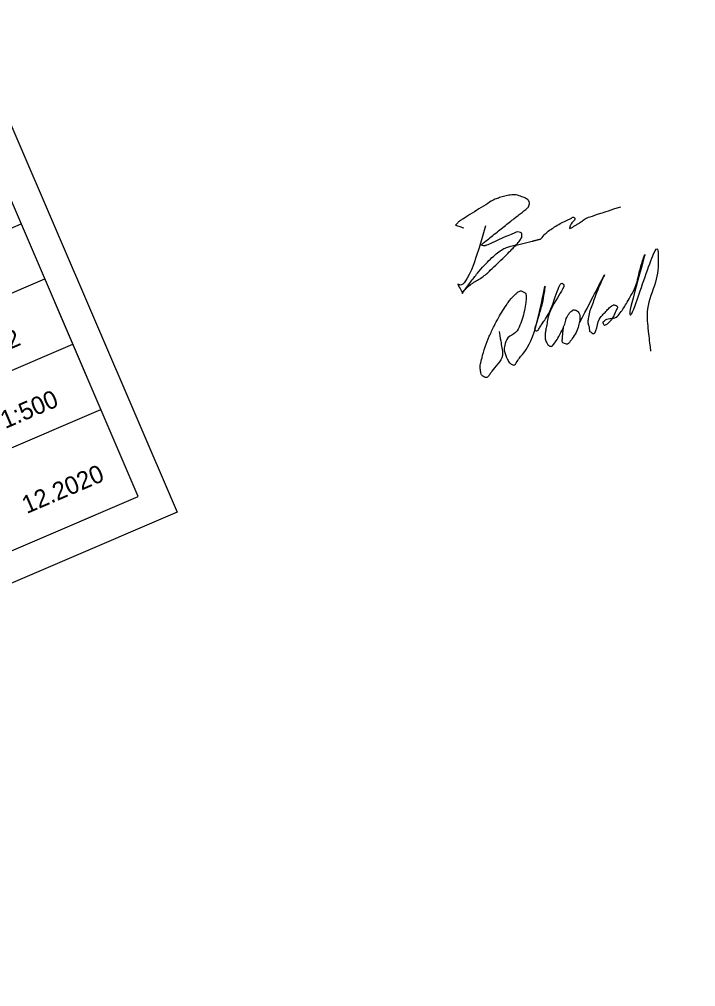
# Model space of a CAD drawing. Extents: x 7500108 to 7500715, y 5768804 to 5769157.
# Drawn here: x 7500658.1 to 7500715.2, y 5768980.6 to 5769062.2 of the extents above; entities that cross this region are included whole.
import ezdxf

# ---------------------------------------------------------------- set-up
doc = ezdxf.new("R2010")
doc.units = 0
for name, color, linetype in [('2_opisy_KD_etap1', 7, 'Continuous'), ('_Wydruk', 7, 'Continuous'), ('DZIALKI', 7, 'Continuous'), ('KLASOUZYTKI', 7, 'Continuous')]:
    doc.layers.add(name, color=color, linetype=linetype)

# ---------------------------------------------------------------- blocks, each defined once
blk = doc.blocks.new('_U10')
at = {"layer": '2_opisy_KD_etap1'}
for points, degree in [([(-5.09, 2.13), (-10.52, -4.72), (-11.31, -2.14), (-10.95, -4.55), (-11.09, -4.5), (-10.83, -4.22), (-10.68, -4.17), (-9.36, -3.72), (-7.98, -3.65), (-6.69, -3.18), (-5.57, -2.77), (-4.45, -2.34), (-3.33, -1.89), (-2.73, -1.64), (-2.17, -1.41), (-1.6, -1.03), (-1.52, -0.98), (-1.49, -0.88), (-1.45, -0.8), (-1.39, -0.68), (-1.29, -0.5), (-1.41, -0.38), (-1.73, -0.09), (-2.09, -0.11), (-2.44, -0.11), (-3.6, -0.09), (-4.77, -0.16), (-5.93, -0.14), (-6.01, -0.14), (-6.09, -0.14), (-6.16, -0.12), (-6.29, -0.09), (-6.54, 0.16), (-6.41, 0.19), (-4.72, 0.67), (-3, 1.14), (-1.29, 1.6), (-0.7, 1.76), (-0.11, 1.91), (0.48, 2.08), (0.73, 2.15), (0.97, 2.4), (1.04, 2.6), (1.14, 2.89), (0.86, 3.3), (0.54, 3.61), (-0.09, 4.22), (-0.74, 4.45), (-1.47, 4.56), (-2.09, 4.65), (-2.73, 4.72), (-3.35, 4.63), (-4.67, 4.43), (-5.99, 4.23), (-7.31, 4.02), (-7.46, 4), (-7.62, 3.97), (-7.77, 3.95), (-7.9, 3.93), (-8.02, 3.87), (-8.15, 3.8), (-8.25, 3.74), (-8.51, 3.69), (-8.43, 3.62), (-8.17, 3.39), (-7.92, 3.17), (-7.66, 2.95)], 3), ([(0.59, -2.08), (1.2, -1.74), (1.86, -1.55), (2.54, -1.42), (3.34, -1.27), (4.13, -1.24), (4.92, -1.21), (5.09, -1.2), (5.35, -1.14), (5.42, -1.25), (5.6, -1.51), (4.84, -1.77), (4.56, -2.04), (4.53, -2.08), (4.49, -2.12), (4.46, -2.16), (4.42, -2.19), (4.39, -2.31), (4.44, -2.31), (4.8, -2.29), (5.16, -2.23), (5.52, -2.18), (6.08, -2.1), (6.63, -1.9), (7.18, -1.95), (8.56, -2.08), (9.93, -2.2), (11.31, -2.33)], 3), ([(-10.95, -4.39), (-5.41, -1.01), (-1.26, -1.82), (0.59, -2.08)], 2)]:
    blk.add_open_spline(points, degree=degree, dxfattribs=at)
blk = doc.blocks.new('_U11')
at = {"layer": '2_opisy_KD_etap1'}
for points in [[(-9.26, 2.84), (-9.44, 2.14), (-9.62, 1.43), (-9.79, 0.73), (-10.07, -0.36), (-11.34, -0.88), (-12.33, -1.5), (-12.58, -1.66), (-12.96, -1.87), (-13.18, -1.61), (-13.33, -1.42), (-13.43, -1.21), (-13.39, -1.02), (-13.28, -0.47), (-13.01, 0.08), (-12.6, 0.59), (-11.62, 1.84), (-10.67, 2.8), (-9.53, 3.77), (-8.68, 4.48), (-7.82, 5.09), (-6.88, 5.7), (-6.47, 5.97), (-6, 6.15), (-5.56, 6.32), (-5.26, 6.44), (-4.81, 6.51), (-4.57, 6.23), (-4.31, 5.92), (-4.49, 5.44), (-4.67, 5.13), (-5.19, 4.23), (-5.83, 3.33), (-6.59, 2.56), (-7.35, 1.8), (-8.68, 1.89), (-9.34, 0.94), (-9.67, 0.47), (-9.68, -0.09), (-9.68, -0.61), (-9.68, -0.88), (-9.66, -1.17), (-9.5, -1.42), (-9.21, -1.86), (-8.51, -1.29), (-8.08, -1.07), (-5.65, 0.18), (-1.16, 6.81), (-2.32, 4.95), (-2.91, 4.02), (-4, 2.69), (-4.91, 1.64), (-4.95, 1.6), (-4.99, 1.56), (-5.02, 1.52), (-5.1, 1.43), (-5.13, 1.2), (-5.05, 1.16), (-4.8, 1.03), (-4.33, 1.43), (-4, 1.63), (-2.39, 2.6), (0.1, 5.57), (0.35, 5.2), (0.59, 4.84), (-2.5, 2.89), (-3.49, 1.34), (-3.79, 0.86), (-4.11, 0.41), (-4.31, -0.11), (-4.4, -0.35), (-4.4, -0.63), (-4.38, -0.88), (-4.36, -1), (-4.34, -1.1), (-4.26, -1.21), (-4.15, -1.34), (-3.97, -1.43), (-3.85, -1.36), (-3.2, -1.01), (-2.55, -0.52), (-1.95, 0), (-1.39, 0.47), (-1.02, 1.07), (-0.39, 1.5), (-0.24, 1.61), (-0.05, 1.63), (0.12, 1.66), (0.2, 1.68), (0.3, 1.7), (0.38, 1.64), (0.81, 1.3), (0.7, 0.53), (0.44, 0.13), (-0.03, -0.56), (-0.69, -1.17), (-1.51, -1.67), (-1.76, -1.82), (-2.1, -1.98), (-2.31, -1.76), (-2.45, -1.63), (-2.62, -1.46), (-2.54, -1.32), (-2.27, -0.82), (-2, -0.32), (-1.73, 0.18)], [(0.39, -0.04), (1.99, 1.27), (3.59, 2.59), (5.19, 3.9), (5.93, 4.51), (3.77, 2.61), (3.14, 1.88), (2.58, 1.23), (1.96, 0.68), (1.49, -0.08), (1.26, -0.46), (1.24, -0.88), (1.15, -1.28), (1.12, -1.39), (1.06, -1.52), (1.12, -1.62), (1.53, -2.38), (2.54, -0.66), (3.35, -0.32), (3.9, -0.08), (4.45, 0.2), (4.99, 0.29), (5.1, 0.31), (5.22, 0.22), (5.32, 0.12), (5.56, -0.14), (5.08, -0.45), (4.85, -0.69), (4.36, -1.19), (3.49, -1.59), (3.1, -1.62), (3, -1.62), (3.01, -1.16), (3.14, -1.11), (3.73, -0.92), (4.68, -1.38), (5.28, -1.04), (5.97, -0.65), (6.64, -0.17), (7.29, 0.32), (8.63, 1.32), (9.78, 3.01), (10.65, 4), (11.87, 5.39), (6.33, -1.48), (6.51, -1.64), (6.73, -1.82), (13.43, 5.79), (12.56, 3.65), (11.54, 1.16), (8.68, -1.39), (7.78, -4.37), (7.53, -5.18), (7.29, -5.99), (7.04, -6.81)]]:
    blk.add_open_spline(points, degree=3, dxfattribs=at)

msp = doc.modelspace()

# ---------------------------------------------------------------- linework, layer by layer
at = {"layer": '_Wydruk'}
msp.add_lwpolyline([(7500603.806, 5768994.339), (7500668.134, 5769021.941), (7500650.853, 5769062.216)], dxfattribs=at)
at = {"layer": 'DZIALKI'}
msp.add_lwpolyline([(7500108.062, 5768940.503), (7500612.863, 5769157.097), (7500671.417, 5769020.629), (7500166.617, 5768804.034)], close=True, dxfattribs=at)
at = {"layer": 'KLASOUZYTKI'}
for p, q in [((7500593.929, 5769017.358), (7500658.257, 5769044.959)), ((7500595.919, 5769012.719), (7500660.248, 5769040.32)), ((7500652.505, 5769030.469), (7500662.614, 5769034.806)), ((7500600.651, 5769001.691), (7500664.98, 5769029.292)), ((7500658.025, 5769017.603), (7500668.134, 5769021.941))]:
    msp.add_line(p, q, dxfattribs=at)
msp.add_lwpolyline([(7500603.806, 5768994.339), (7500668.134, 5769021.941), (7500653.956, 5769054.985), (7500589.627, 5769027.383)], close=True, dxfattribs=at)

# ---------------------------------------------------------------- block references
at = {"layer": '2_opisy_KD_etap1', "xscale": 0.6794772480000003, "yscale": 0.6794772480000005, "rotation": 23.222710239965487}
for name, p in [('_U10', (7500701.183, 5769044.824)), ('_U11', (7500705.141, 5769036.562))]:
    msp.add_blockref(name, p, dxfattribs=at)

# ---------------------------------------------------------------- texts
at = {"layer": 'KLASOUZYTKI'}
for s, p in [('S-2', (7500655.459, 5769033.54)), ('1:500', (7500656.909, 5769027.633)), ('12.2020', (7500658.722, 5769020.454))]:
    msp.add_text(s, height=1.5, rotation=23.22271, dxfattribs=at).set_placement(p)

doc.saveas('drawing.dxf')
